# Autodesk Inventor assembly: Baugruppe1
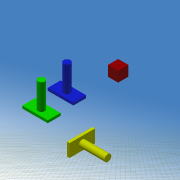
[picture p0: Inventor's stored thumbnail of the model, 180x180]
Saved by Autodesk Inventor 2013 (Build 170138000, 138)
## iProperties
Created: 2012-09
Part Number: Baugruppe1
Document SubType Name: Assembly
Designer: tvs
Mass: 376.389 g
Surface Area: 733.425 cm^2
Volume: 376.389 cm^3
Density: 1 g/cm^3
Author: tvs
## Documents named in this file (3)
- I:\3D\Konstruktion\tvs\Basteleien\Animation\Baugruppe1.iam
- I:\3D\Konstruktion\tvs\Basteleien\Animation\Stempel.ipt
- I:\3D\Konstruktion\tvs\Basteleien\Animation\Wuerfel.ipt
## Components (4 placed, 2 different names)
1. Stempel:1 — Passend:1, Passend:2, Passend:3, Passend:4, Passend:5, Fluchtend:1, Passend:6, Passend:7, Passend:9, Fluchtend:3, Passend:2
2. Wuerfel:1 — Passend:1, Passend:2, Passend:3
3. Stempel:2 — Passend:6, Passend:2, Passend:7, Passend:8
4. Stempel:3 — Passend:8, Passend:9, Fluchtend:3
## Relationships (12: Mate 10, Flush 2)
- Passend:1 [Mate]: Stempel:1 ↔ Wuerfel:1
- Passend:2 [Mate]: Stempel:1 ↔ Wuerfel:1
- Passend:3 [Mate]: Stempel:1 ↔ Wuerfel:1
- Passend:4 [Mate]: Stempel:1
- Passend:5 [Mate]: Stempel:1
- Fluchtend:1 [Flush]: Stempel:1
- Passend:6 [Mate]: Stempel:1 ↔ Stempel:2
- Passend:2 [Mate]: Stempel:1 ↔ Stempel:2
- Passend:7 [Mate]: Stempel:1 ↔ Stempel:2
- Passend:8 [Mate]: Stempel:2 ↔ Stempel:3
- Passend:9 [Mate]: Stempel:1 ↔ Stempel:3
- Fluchtend:3 [Flush]: Stempel:1 ↔ Stempel:3
